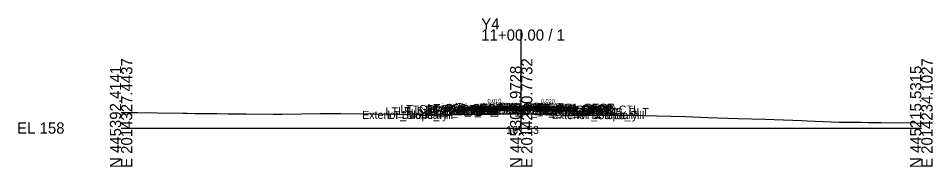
# Model space of a CAD drawing. Extents: x -26 to 203, y -10 to 4021.
# Drawn here: x -25.7 to 202.8, y 1990.3 to 2027.5 of the extents above; entities that cross this region are included whole.
import ezdxf

# ---------------------------------------------------------------- set-up
doc = ezdxf.new("R2010")
doc.units = 0
for name, color, linetype in [('Default', 7, 'Continuous'), ('Exist Cross Section Cell', 7, 'Continuous'), ('Exist XS Center Line Elevation Label', 7, 'Continuous'), ('Exist XS Ground Line', 7, 'Continuous'), ('Prop CMT Pvmt Course 1', 7, 'Continuous'), ('Prop CMT Pvmt Course 2', 7, 'Continuous'), ('Prop CMT Pvmt Course 3', 7, 'Continuous'), ('Prop CMT Pvmt Surface', 7, 'Continuous'), ('Prop CMT Pvmt Surface Shoulder', 7, 'Continuous'), ('Prop CMT Shld Paved Course 1', 7, 'Continuous'), ('Prop CMT Shld Paved Course 2', 7, 'Continuous'), ('Prop CMT Shld Paved Course 3', 7, 'Continuous'), ('Prop CMT Slope Grass', 7, 'Continuous'), ('Prop CMT Subgrade Earthwork', 7, 'Continuous'), ('Prop XS Earthwork Shape', 7, 'Continuous'), ('Prop XS SE Text', 7, 'Continuous'), ('Prop XS Side Slope Text', 7, 'Continuous'), ('Scratch_Level_0', 7, 'Continuous')]:
    doc.layers.add(name, color=color, linetype=linetype)

msp = doc.modelspace()

# ---------------------------------------------------------------- linework, layer by layer
at = {"layer": 'Exist Cross Section Cell'}
for p, q in [((100, 2000), (100, 2024.7)), ((0, 2000), (100, 2000)), ((100, 2000), (200, 2000))]:
    msp.add_line(p, q, dxfattribs=at)
at = {"layer": 'Exist XS Ground Line'}
msp.add_lwpolyline([(0, 2003.92), (1.68, 2003.89), (4.09, 2003.89), (9.08, 2003.85), (15.4, 2003.69), (16.49, 2003.7), (18.55, 2003.67), (23.89, 2003.68), (26.7, 2003.58), (31.29, 2003.53), (38.01, 2003.46), (38.69, 2003.44), (40.29, 2003.47), (49.81, 2003.66), (54.91, 2003.62), (62.87, 2003.56), (68.71, 2003.46), (74.7, 2003.31), (79.07, 2003.26), (83.89, 2003.37), (88.77, 2003.44), (94.36, 2003.48), (99.17, 2003.55), (100, 2003.53), (106.64, 2003.39), (110.65, 2003.24), (116.88, 2003.23), (126.06, 2003.23), (127.24, 2003.23), (127.77, 2003.22), (130.2, 2003.17), (141.07, 2002.91), (146.61, 2002.63), (154.13, 2002.35), (160.92, 2002.24), (170.19, 2001.85), (171.43, 2001.81), (179.48, 2001.5), (185.02, 2001.46), (186.74, 2001.4), (189.98, 2001.38), (198.6, 2001.28), (200, 2001.22)], dxfattribs=at)
at = {"layer": 'Prop CMT Pvmt Course 1'}
for points in [[(100, 2005.37), (86.47, 2005.24)], [(86.47, 2005.24), (86.47, 2004.99)], [(86.47, 2004.99), (100, 2005.12)], [(100, 2005.12), (100, 2005.37)], [(100, 2005.37), (113.3, 2005.11)], [(100, 2005.12), (100, 2005.37)], [(113.3, 2004.86), (100, 2005.12)], [(113.3, 2005.11), (113.3, 2004.86)]]:
    msp.add_lwpolyline(points, dxfattribs=at)
msp.add_lwpolyline([(100, 2005.12), (100, 2005.25), (100, 2005.25), (100, 2005.12)], close=True, dxfattribs=at)
msp.add_lwpolyline([(100, 2005.12), (100, 2005.25), (100, 2005.25), (100, 2005.12)], close=True, dxfattribs=at)
at = {"layer": 'Prop CMT Pvmt Course 2'}
for points in [[(100, 2005.12), (86.47, 2004.99)], [(86.47, 2004.99), (86.47, 2004.65)], [(86.47, 2004.65), (100, 2004.79)], [(100, 2004.79), (100, 2005.12)], [(100, 2004.79), (100, 2005.12)], [(100, 2005.12), (113.3, 2004.86)], [(113.3, 2004.52), (100, 2004.79)], [(113.3, 2004.86), (113.3, 2004.52)]]:
    msp.add_lwpolyline(points, dxfattribs=at)
at = {"layer": 'Prop CMT Pvmt Course 3'}
for points in [[(100, 2004.79), (86.47, 2004.65)], [(86.47, 2004.65), (86.47, 2004.32)], [(86.47, 2004.32), (100, 2004.46)], [(100, 2004.46), (100, 2004.79)], [(100, 2004.79), (113.3, 2004.52)], [(100, 2004.46), (100, 2004.79)], [(113.3, 2004.19), (100, 2004.46)], [(113.3, 2004.52), (113.3, 2004.19)]]:
    msp.add_lwpolyline(points, dxfattribs=at)
at = {"layer": 'Prop CMT Pvmt Surface'}
for points in [[(100, 2005.37), (86.47, 2005.24)], [(100, 2005.37), (113.3, 2005.11)]]:
    msp.add_lwpolyline(points, dxfattribs=at)
at = {"layer": 'Prop CMT Pvmt Surface Shoulder'}
for points in [[(86.47, 2005.24), (86.47, 2005.24)], [(113.3, 2005.11), (113.3, 2005.11)]]:
    msp.add_lwpolyline(points, dxfattribs=at)
at = {"layer": 'Prop CMT Shld Paved Course 1'}
for points in [[(86.47, 2005.24), (86.21, 2004.98)], [(86.21, 2004.98), (86.47, 2004.99)], [(86.47, 2005.24), (86.47, 2005.24)], [(86.47, 2004.99), (86.47, 2005.24)], [(113.3, 2005.11), (113.3, 2005.11)], [(113.3, 2005.11), (113.55, 2004.85)], [(113.3, 2004.86), (113.3, 2005.11)], [(113.55, 2004.85), (113.3, 2004.86)]]:
    msp.add_lwpolyline(points, dxfattribs=at)
at = {"layer": 'Prop CMT Shld Paved Course 2'}
for points in [[(86.47, 2004.99), (86.21, 2004.98), (85.87, 2004.64)], [(85.87, 2004.64), (86.47, 2004.65)], [(86.47, 2004.65), (86.47, 2004.99)], [(113.3, 2004.86), (113.55, 2004.85), (113.89, 2004.51)], [(113.3, 2004.52), (113.3, 2004.86)], [(113.89, 2004.51), (113.3, 2004.52)]]:
    msp.add_lwpolyline(points, dxfattribs=at)
at = {"layer": 'Prop CMT Shld Paved Course 3'}
for points in [[(85.03, 2004.29), (86.47, 2004.32)], [(86.47, 2004.65), (85.87, 2004.64), (85.53, 2004.3)], [(86.47, 2004.32), (86.47, 2004.65)], [(113.3, 2004.19), (113.3, 2004.52)], [(113.3, 2004.52), (113.89, 2004.51), (114.23, 2004.17)], [(114.73, 2004.16), (113.3, 2004.19)]]:
    msp.add_lwpolyline(points, dxfattribs=at)
at = {"layer": 'Prop CMT Slope Grass'}
for points in [[(86.47, 2005.24), (80.47, 2004.76), (76.09, 2003.3)], [(113.3, 2005.11), (119.3, 2004.63), (123.48, 2003.23)]]:
    msp.add_lwpolyline(points, dxfattribs=at)
at = {"layer": 'Prop CMT Subgrade Earthwork'}
for points in [[(85.03, 2004.29), (78.69, 2004.16)], [(86.47, 2004.32), (85.03, 2004.29)], [(100, 2004.46), (86.47, 2004.32)], [(100, 2004.46), (113.3, 2004.19)], [(113.3, 2004.19), (114.73, 2004.16)], [(114.73, 2004.16), (121.08, 2004.03)]]:
    msp.add_lwpolyline(points, dxfattribs=at)
at = {"layer": 'Prop XS Earthwork Shape'}
msp.add_lwpolyline([(94.36, 2003.48), (99.17, 2003.55), (100, 2003.53), (106.64, 2003.39), (110.65, 2003.24), (116.88, 2003.23), (123.48, 2003.23), (121.08, 2004.03), (114.73, 2004.16), (113.3, 2004.19), (100, 2004.46), (86.47, 2004.32), (85.03, 2004.29), (78.69, 2004.16), (76.09, 2003.3), (79.07, 2003.26), (83.89, 2003.37), (88.77, 2003.44)], close=True, dxfattribs=at)

# ---------------------------------------------------------------- texts
at = {"layer": 'Default'}
msp.add_text('-', height=0.0001, dxfattribs=at).set_placement((0, 2000))
at = {"layer": 'Exist Cross Section Cell'}
for s, p in [('Y4', (90, 2024.7)), ('11+00.00 / 1', (90, 2021.9)), ('EL 158', (-26, 1998.6))]:
    msp.add_text(s, height=2.8, dxfattribs=at).set_placement(p)
for s, p in [('E 2014327.4437', (2.8, 1990)), ('E 2014280.7732', (102.8, 1990)), ('E 2014234.1027', (202.8, 1990)), ('N 445392.4141', (0, 1990)), ('N 445303.9728', (100, 1990)), ('N 445215.5315', (200, 1990))]:
    msp.add_text(s, height=2.8, rotation=90, dxfattribs=at).set_placement(p)
at = {"layer": 'Exist XS Center Line Elevation Label'}
msp.add_text('161.53', height=2, dxfattribs=at).set_placement((96.23, 1998.53))
at = {"layer": 'Prop XS SE Text'}
for s, rotation, p in [('0.010', 0.5729, (91.59, 2006.29)), ('0.020', 358.8542, (104.92, 2006.27))]:
    msp.add_text(s, height=1, rotation=rotation, dxfattribs=at).set_placement(p)
at = {"layer": 'Prop XS Side Slope Text'}
for rotation, p in [(18.4332, (77.29, 2004.49)), (341.5668, (120.87, 2004.89))]:
    msp.add_text('3:1', height=1, rotation=rotation, dxfattribs=at).set_placement(p)
at = {"layer": 'Scratch_Level_0'}
for s, p in [('Exterior Boundary', (60.23, 2002.3)), ('LT_Sub_OSS_DLT', (66.09, 2003.16)), ('LT_Slope_Fill', (66.61, 2002.3)), ('LT_Sub_Trench_Out', (69.24, 2003.29)), ('LT_GS_OS_CTL', (69.84, 2003.76)), ('LT_PS3_Shelf_Out', (71.36, 2003.63)), ('LT_PS3_OEOP', (76.11, 2003.64)), ('LT_PS2_OEOP', (76.45, 2003.98)), ('LT_Sub_OEOT', (76.55, 2003.32)), ('LT_PV2_OEOT', (76.64, 2003.99)), ('LT_PV3_OEOT', (76.64, 2003.65)), ('LT_PV1_OEOT', (77.21, 2004.24)), ('LT_PS1_OEOP', (77.27, 2004.24)), ('RT_Sub_OEEOP', (89.17, 2003.46)), ('LT_Sub_OEEOP', (89.21, 2003.46)), ('RT_PV2_OEEOP', (89.26, 2004.12)), ('RT_PV3_OEEOP', (89.26, 2003.79)), ('LT_PV2_OEEOP', (89.31, 2004.12)), ('LT_PV3_OEEOP', (89.31, 2003.79)), ('RT_PV1_OEEOP', (89.83, 2004.25)), ('LT_PV1_OEEOP', (89.87, 2004.25)), ('RT_PV2_IEEOP', (89.91, 2004.12)), ('LT_PV2_IEEOP', (89.95, 2004.12)), ('RT_PV1_IEEOP', (90.47, 2004.25)), ('LT_PV1_IEEOP', (90.52, 2004.25)), ('PV2_PGL', (93.91, 2004.12)), ('PV1_PGL', (94.47, 2004.37)), ('RT_Sub_Trench_Out', (98.89, 2003.16)), ('RT_PS3_Shelf_Out', (100.33, 2003.5)), ('RT_Sub_OEOT', (103.33, 2003.19)), ('RT_PV2_OEOT', (103.43, 2003.86)), ('RT_PV3_OEOT', (103.43, 2003.52)), ('RT_PS2_OEOP', (103.74, 2003.85)), ('RT_PV1_OEOT', (103.99, 2004.11)), ('RT_PS1_OEOP', (104.06, 2004.11)), ('RT_PS3_OEOP', (104.08, 2003.51)), ('Exterior Boundary', (107.62, 2002.23)), ('RT_Sub_OSS_DLT', (108.43, 2003.03)), ('RT_GS_OS_CTL', (108.62, 2003.63)), ('RT_Slope_Fill', (113.95, 2002.23))]:
    msp.add_text(s, height=2, dxfattribs=at).set_placement(p)

doc.saveas('drawing.dxf')
